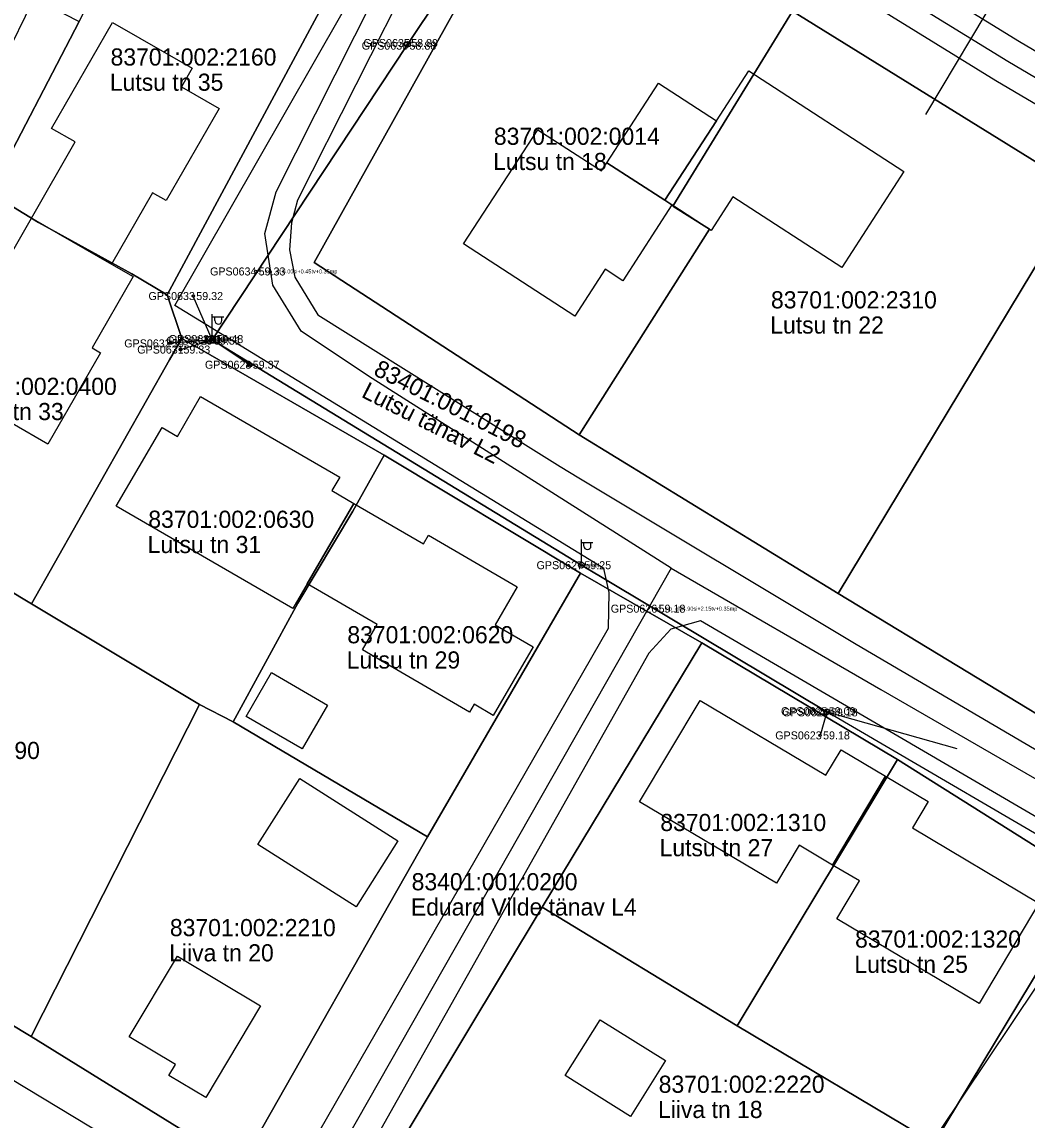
# Model space of a CAD drawing. Extents: x 580119 to 583377, y 6518915 to 6520820.
# Drawn here: x 581772.7 to 581860.5, y 6520277 to 6520373 of the extents above; entities that cross this region are included whole.
import ezdxf

# ---------------------------------------------------------------- set-up
doc = ezdxf.new("R2010")
doc.units = 0
for name, color, linetype in [('ELRAJATISMP', 7, 'Continuous'), ('Hoone Elu- või ühiskondlik hoone', 7, 'Continuous'), ('Hoone Kõrval- või tootmishoone', 7, 'Continuous'), ('L_AADRESS', 7, 'Continuous'), ('MAAMUDEL', 7, 'Continuous'), ('MOOTKORG-EH2000', 7, 'Continuous'), ('MOOTMPUNKT', 7, 'Continuous'), ('MOOTNR', 7, 'Continuous'), ('MPOHULIIN', 7, 'Continuous'), ('PIIR', 7, 'Continuous'), ('POST', 7, 'Continuous'), ('Rippe kõrgus', 7, 'Continuous'), ('SIOHULIIN', 7, 'Continuous'), ('SIRAJATIS', 7, 'Continuous'), ('Tee Liiklusala', 7, 'Continuous'), ('Tee Tänav Püsikate', 7, 'Continuous'), ('TUNNUS', 7, 'Continuous')]:
    doc.layers.add(name, color=color, linetype=linetype)

msp = doc.modelspace()

# ---------------------------------------------------------------- linework, layer by layer
at = {"layer": 'ELRAJATISMP'}
for p, q in [((581789.158, 6520345.511), (581789.158, 6520344.914)), ((581789.429, 6520345.511), (581789.429, 6520344.914))]:
    msp.add_line(p, q, dxfattribs=at)
msp.add_lwpolyline([(581788.696, 6520345.511), (581789.891, 6520345.511), (581789.891, 6520344.914), (581788.696, 6520344.914)], close=True, dxfattribs=at)
at = {"layer": 'Hoone Elu- või ühiskondlik hoone'}
for points in [[(581789.897, 6520365.456), (581785.267, 6520357.388), (581784.066, 6520358.074), (581780.484, 6520351.835), (581773.488, 6520355.852), (581777.309, 6520362.515), (581775.246, 6520363.708), (581780.566, 6520372.96), (581787.532, 6520368.967), (581786.605, 6520367.341)], [(581849.757, 6520359.929), (581844.318, 6520351.547), (581834.806, 6520357.717), (581832.902, 6520354.782), (581829.475, 6520357.006), (581828.842, 6520357.417), (581833.361, 6520364.377), (581836.189, 6520368.733)], [(581817.758, 6520363.59), (581823.32, 6520359.982), (581823.786, 6520360.7), (581828.842, 6520357.417), (581829.475, 6520357.006), (581825.18, 6520350.387), (581823.634, 6520351.39), (581820.977, 6520347.297), (581811.266, 6520353.598)], [(581782.362, 6520350.757), (581778.776, 6520344.511), (581779.521, 6520344.084), (581774.927, 6520336.097), (581771.788, 6520337.897), (581770.984, 6520336.504), (581764.038, 6520340.495), (581769.406, 6520349.847), (581769.887, 6520349.572), (581773.488, 6520355.852), (581780.484, 6520351.835)], [(581788.274, 6520340.264), (581800.435, 6520333.198), (581799.755, 6520332.025), (581801.668, 6520330.914), (581797.585, 6520323.885), (581796.321, 6520321.71), (581780.903, 6520330.666), (581784.9, 6520337.536), (581786.238, 6520336.758)], [(581801.668, 6520330.914), (581807.753, 6520327.378), (581808.187, 6520328.122), (581815.958, 6520323.603), (581814.029, 6520320.283), (581817.344, 6520318.359), (581813.862, 6520312.365), (581812.178, 6520313.343), (581811.785, 6520312.668), (581802.41, 6520318.115), (581803.699, 6520320.333), (581797.585, 6520323.885)], [(581831.936, 6520313.685), (581842.938, 6520307.135), (581844.272, 6520309.373), (581848.153, 6520307.062), (581843.524, 6520299.283), (581840.601, 6520301.023), (581838.615, 6520297.688), (581826.651, 6520304.808)], [(581861.562, 6520295.955), (581856.334, 6520287.167), (581843.894, 6520294.572), (581845.861, 6520297.893), (581843.524, 6520299.283), (581848.153, 6520307.062), (581851.891, 6520304.836), (581850.522, 6520302.527)], [(581793.512, 6520286.959), (581788.715, 6520278.954), (581785.489, 6520280.884), (581786.062, 6520281.845), (581782.021, 6520284.264), (581786.238, 6520291.31)]]:
    msp.add_lwpolyline(points, close=True, dxfattribs=at)
at = {"layer": 'Hoone Kõrval- või tootmishoone'}
for points in [[(581773.527, 6520374.677), (581771.164, 6520369.845), (581758.583, 6520375.994), (581760.951, 6520380.836)], [(581828.842, 6520357.417), (581823.786, 6520360.7), (581828.307, 6520367.654), (581833.361, 6520364.377)], [(581799.377, 6520313.278), (581797.15, 6520309.442), (581792.248, 6520312.288), (581794.476, 6520316.124)], [(581796.933, 6520306.849), (581805.518, 6520301.405), (581801.857, 6520295.631), (581793.272, 6520301.076)], [(581828.912, 6520282.18), (581825.861, 6520277.308), (581820.151, 6520280.885), (581823.202, 6520285.757)]]:
    msp.add_lwpolyline(points, close=True, dxfattribs=at)
at = {"layer": 'MOOTMPUNKT'}
for centre in [(581806.274, 6520370.939), (581806.424, 6520371.167), (581793.083, 6520351.193), (581787.632, 6520349.042), (581785.515, 6520344.9), (581789.188, 6520345.144), (581789.4, 6520345.282), (581786.511, 6520344.363), (581792.568, 6520343.035), (581821.56, 6520325.505), (581828.05, 6520321.704), (581842.927, 6520312.739), (581843.11, 6520312.635), (581842.429, 6520310.622)]:
    msp.add_circle(centre, 0.1, dxfattribs=at)
at = {"layer": 'MPOHULIIN'}
for p, q in [((581789.294, 6520345.213), (581787.632, 6520349.042)), ((581843.019, 6520312.687), (581842.429, 6520310.622))]:
    msp.add_line(p, q, dxfattribs=at)
for points in [[(581789.294, 6520345.213), (581806.349, 6520371.053), (581823.377, 6520396.506), (581838.047, 6520387.917), (581858.295, 6520376.01), (581878.688, 6520363.88), (581896.571, 6520352.922)], [(581867.762, 6520298.217), (581843.019, 6520312.687), (581821.56, 6520325.505), (581789.294, 6520345.213), (581785.515, 6520344.9)], [(581841.646, 6520259.228), (581850.68, 6520272.732), (581867.762, 6520298.217)]]:
    msp.add_lwpolyline(points, dxfattribs=at)
at = {"layer": 'PIIR'}
for points in [[(581744.38, 6520390.07), (581777.64, 6520373.06), (581769.84, 6520358.07), (581768.32, 6520355.34), (581735.49, 6520372.19)], [(581769.84, 6520358.07), (581777.64, 6520373.06), (581785.47, 6520388.28), (581801.36, 6520378.94), (581785.35, 6520349.14), (581782.27, 6520350.98), (581774.1, 6520355.46)], [(581817.44, 6520386.49), (581840.03, 6520373.94), (581829.56, 6520356.9), (581832.75, 6520354.9), (581821.38, 6520336.91), (581798.19, 6520351.98)], [(581798.19, 6520351.98), (581821.38, 6520336.91), (581844, 6520323.04), (581878.03, 6520302.4), (581885.96, 6520304.82), (581899.19, 6520326.8), (581895.57, 6520340), (581865.29, 6520358.29), (581840.03, 6520373.94), (581817.44, 6520386.49)], [(581832.75, 6520354.9), (581829.56, 6520356.9), (581840.03, 6520373.94), (581865.29, 6520358.29), (581844, 6520323.04), (581821.38, 6520336.91)], [(581759.06, 6520337.58), (581768.32, 6520355.34), (581769.84, 6520358.07), (581774.1, 6520355.46), (581782.27, 6520350.98), (581785.35, 6520349.14), (581786.62, 6520345.32), (581785.55, 6520343.45), (581773.48, 6520322.14), (581756.66, 6520332.23)], [(581865.29, 6520358.29), (581895.57, 6520340), (581899.19, 6520326.8), (581885.96, 6520304.82), (581878.03, 6520302.4), (581844, 6520323.04)], [(581785.55, 6520343.45), (581786.62, 6520345.32), (581804.32, 6520335.14), (581801.57, 6520330.22), (581796.78, 6520322.19), (581791.12, 6520311.82), (581788.16, 6520313.33), (581773.48, 6520322.14)], [(581796.78, 6520322.19), (581801.57, 6520330.22), (581804.32, 6520335.14), (581821.48, 6520324.8), (581808.12, 6520301.74), (581791.12, 6520311.82)], [(581773.48, 6520322.14), (581788.16, 6520313.33), (581773.45, 6520284.3), (581741.73, 6520303.41), (581756.66, 6520332.23)], [(581801.15, 6520267.32), (581791.76, 6520272.95), (581808.12, 6520301.74), (581821.48, 6520324.8), (581832.08, 6520318.73), (581818.12, 6520295.6)], [(581832.08, 6520318.73), (581849.2, 6520308.51), (581835.18, 6520285.22), (581818.12, 6520295.6)], [(581788.16, 6520313.33), (581791.12, 6520311.82), (581808.12, 6520301.74), (581791.76, 6520272.95), (581773.45, 6520284.3)], [(581849.2, 6520308.51), (581866.2, 6520297.82), (581852.4, 6520274.95), (581835.18, 6520285.22)], [(581866.2, 6520297.82), (581884.83, 6520286.51), (581870.83, 6520263.78), (581852.4, 6520274.95)], [(581818.12, 6520295.6), (581835.18, 6520285.22), (581852.4, 6520274.95), (581841.97, 6520255.88), (581832.33, 6520260.46), (581827.76, 6520250.96), (581804.72, 6520265.17), (581801.15, 6520267.32)]]:
    msp.add_lwpolyline(points, close=True, dxfattribs=at)
for points in [[(581953.73, 6520280.26), (581942.22, 6520287.85), (581915, 6520303.97), (581907.15, 6520308.24), (581895.61, 6520303.69), (581890.17, 6520295.02), (581885.52, 6520287.54), (581884.83, 6520286.51), (581866.2, 6520297.82), (581849.2, 6520308.51), (581832.08, 6520318.73), (581821.48, 6520324.8), (581804.32, 6520335.14), (581786.62, 6520345.32), (581785.35, 6520349.14), (581801.36, 6520378.94)], [(581641.44, 6520358.2), (581663.75, 6520346.68), (581696.78, 6520330.58), (581710.47, 6520322.41), (581741.73, 6520303.41), (581773.45, 6520284.3), (581791.76, 6520272.95), (581801.15, 6520267.32), (581804.72, 6520265.17), (581827.76, 6520250.96), (581836.91, 6520245.57), (581863.22, 6520229.79), (581868.94, 6520226.76), (581900.21, 6520207.51)]]:
    msp.add_lwpolyline(points, dxfattribs=at)
at = {"layer": 'POST'}
for p, q in [((581789.294, 6520345.463), (581789.294, 6520347.463)), ((581789.294, 6520347.213), (581790.294, 6520347.213)), ((581789.52, 6520346.892), (581789.52, 6520347.213)), ((581790.133, 6520346.892), (581790.133, 6520347.213)), ((581789.294, 6520345.213), (581789.294, 6520345.213)), ((581821.56, 6520325.755), (581821.56, 6520327.755)), ((581821.56, 6520327.505), (581822.56, 6520327.505)), ((581821.787, 6520327.184), (581821.787, 6520327.505)), ((581822.4, 6520327.184), (581822.4, 6520327.505)), ((581821.56, 6520325.505), (581821.56, 6520325.505))]:
    msp.add_line(p, q, dxfattribs=at)
for points in [[(581786.511, 6520344.363), (581789.294, 6520345.213)], [(581792.568, 6520343.035), (581789.294, 6520345.213)]]:
    msp.add_lwpolyline(points, dxfattribs=at)
for centre, radius in [((581806.349, 6520371.053), 0.25), ((581789.294, 6520345.213), 0.25), ((581786.511, 6520344.363), 0.125), ((581786.511, 6520344.363), 0.105), ((581786.511, 6520344.363), 0.0851), ((581786.511, 6520344.363), 0.0651), ((581786.511, 6520344.363), 0.0451), ((581786.511, 6520344.363), 0.0251), ((581786.511, 6520344.363), 0.00511), ((581792.568, 6520343.035), 0.2), ((581821.56, 6520325.505), 0.25), ((581843.019, 6520312.687), 0.25)]:
    msp.add_circle(centre, radius, dxfattribs=at)
for centre in [(581789.827, 6520346.892), (581822.093, 6520327.184)]:
    msp.add_arc(centre, 0.306, 180, 0, dxfattribs=at)
at = {"layer": 'SIOHULIIN'}
msp.add_line((581843.019, 6520312.687), (581854.376, 6520309.468), dxfattribs=at)
msp.add_lwpolyline([(581851.668, 6520364.915), (581858.295, 6520376.01), (581838.047, 6520387.917), (581823.377, 6520396.506), (581806.349, 6520371.053), (581789.294, 6520345.213), (581821.56, 6520325.505), (581843.019, 6520312.687)], dxfattribs=at)
at = {"layer": 'SIRAJATIS'}
msp.add_lwpolyline([(581788.794, 6520345.513), (581789.794, 6520345.513), (581789.794, 6520344.913), (581788.794, 6520344.913)], close=True, dxfattribs=at)
for centre, radius in [((581789.094, 6520345.213), 0.0304), ((581789.094, 6520345.213), 0.029), ((581789.094, 6520345.213), 0.0277), ((581789.094, 6520345.213), 0.0263), ((581789.094, 6520345.213), 0.0249), ((581789.094, 6520345.213), 0.0236), ((581789.094, 6520345.213), 0.0222), ((581789.094, 6520345.213), 0.0209), ((581789.094, 6520345.213), 0.0195), ((581789.094, 6520345.213), 0.0181), ((581789.094, 6520345.213), 0.0168), ((581789.094, 6520345.213), 0.0154), ((581789.094, 6520345.213), 0.014), ((581789.094, 6520345.213), 0.0127), ((581789.094, 6520345.213), 0.0113), ((581789.094, 6520345.213), 0.00996), ((581789.094, 6520345.213), 0.0086), ((581789.094, 6520345.213), 0.00724), ((581789.094, 6520345.213), 0.00587), ((581789.094, 6520345.213), 0.00451), ((581789.094, 6520345.213), 0.00315), ((581789.094, 6520345.213), 0.00179), ((581789.094, 6520345.213), 0.000426), ((581789.494, 6520345.213), 0.0304), ((581789.494, 6520345.213), 0.029), ((581789.494, 6520345.213), 0.0277), ((581789.494, 6520345.213), 0.0263), ((581789.494, 6520345.213), 0.0249), ((581789.494, 6520345.213), 0.0236), ((581789.494, 6520345.213), 0.0222), ((581789.494, 6520345.213), 0.0209), ((581789.494, 6520345.213), 0.0195), ((581789.494, 6520345.213), 0.0181), ((581789.494, 6520345.213), 0.0168), ((581789.494, 6520345.213), 0.0154), ((581789.494, 6520345.213), 0.014), ((581789.494, 6520345.213), 0.0127), ((581789.494, 6520345.213), 0.0113), ((581789.494, 6520345.213), 0.00996), ((581789.494, 6520345.213), 0.0086), ((581789.494, 6520345.213), 0.00724), ((581789.494, 6520345.213), 0.00587), ((581789.494, 6520345.213), 0.00451), ((581789.494, 6520345.213), 0.00315), ((581789.494, 6520345.213), 0.00179), ((581789.494, 6520345.213), 0.000426)]:
    msp.add_circle(centre, radius, dxfattribs=at)
at = {"layer": 'Tee Liiklusala'}
for points in [[(581708.973, 6520318.471), (581787.026, 6520271.325), (581789.162, 6520270.507), (581791.383, 6520270.184), (581793.899, 6520270.794), (581795.507, 6520271.692), (581797.15, 6520273.396), (581823.944, 6520319.987), (581823.993, 6520323.124), (581823.536, 6520325.218), (581786.005, 6520348.211), (581807.901, 6520386.495)], [(581843.846, 6520381.181), (581859.867, 6520371.288), (581885.234, 6520356.315), (581895.768, 6520349.311), (581899.82, 6520345.619), (581902.264, 6520341.18), (581903.771, 6520334.245), (581905.896, 6520322.742), (581907.129, 6520319.737), (581908.783, 6520316.908), (581910.786, 6520315.323), (581915.903, 6520312.25), (581921.785, 6520309.332), (581947.382, 6520293.091)], [(581806.937, 6520377.638), (581796.746, 6520357.421), (581796.211, 6520355.457), (581796.054, 6520353.093), (581796.496, 6520350.692), (581798.527, 6520347.398), (581811.066, 6520339.54), (581819.697, 6520334.131), (581821.327, 6520333.154), (581845.583, 6520318.613), (581875.933, 6520300.79)], [(581883.108, 6520352.925), (581857.799, 6520367.864), (581841.674, 6520377.821)], [(581883.73, 6520290.39), (581831.98, 6520320.646), (581829.373, 6520319.902), (581827.47, 6520317.82), (581801.546, 6520271.778), (581800.552, 6520269.623), (581800.234, 6520267.264), (581800.633, 6520264.933), (581801.205, 6520263.087), (581802.352, 6520262.069), (581822.226, 6520250.366), (581872.961, 6520219.702)]]:
    msp.add_lwpolyline(points, dxfattribs=at)
at = {"layer": 'Tee Tänav Püsikate'}
for points in [[(581829.397, 6520325.257), (581818.112, 6520332.413), (581802.942, 6520342.026), (581797.052, 6520345.979), (581794.581, 6520349.987), (581793.881, 6520354.518), (581794.87, 6520358.142), (581805.199, 6520378.634), (581809.475, 6520385.247), (581812.613, 6520388.504), (581816.168, 6520390.211), (581820.374, 6520391.246), (581824.109, 6520390.415), (581827.723, 6520388.924), (581832.69, 6520386.312), (581842.76, 6520379.501), (581858.833, 6520369.576), (581884.171, 6520354.62), (581894.534, 6520347.73), (581898.228, 6520344.364), (581900.371, 6520340.471), (581901.81, 6520333.851), (581904.244, 6520320.676), (581905.593, 6520312.247)], [(581829.397, 6520325.257), (581794.4, 6520263.722)], [(581829.397, 6520325.257), (581847.74, 6520314.641), (581881.43, 6520295.181), (581886.42, 6520300.232), (581896.888, 6520308.777), (581900.557, 6520310.703), (581905.593, 6520312.247)]]:
    msp.add_lwpolyline(points, dxfattribs=at)

# ---------------------------------------------------------------- texts
at = {"layer": 'L_AADRESS'}
for s, p in [('Lutsu tn 35', (581780.337, 6520366.992)), ('Lutsu tn 18', (581813.847, 6520360.061)), ('Lutsu tn 22', (581838.072, 6520345.758)), ('Lutsu tn 33', (581766.377, 6520338.193)), ('Lutsu tn 31', (581783.637, 6520326.568)), ('Lutsu tn 29', (581801.037, 6520316.47)), ('Lutsu tn 27', (581828.397, 6520300.053)), ('Eduard Vilde tänav L4', (581806.657, 6520294.871)), ('Liiva tn 20', (581785.522, 6520290.86)), ('Lutsu tn 25', (581845.427, 6520289.859)), ('Liiva tn 18', (581828.257, 6520277.162))]:
    msp.add_text(s, height=1.5, dxfattribs=at).set_placement(p)
msp.add_text('Lutsu tänav L2', height=1.5, rotation=333.18291, dxfattribs=at).set_placement((581802.242, 6520340.249))
at = {"layer": 'MAAMUDEL'}
for p in [(581789.188, 6520344.969), (581789.4, 6520345.107), (581821.56, 6520325.33)]:
    msp.add_text(' kaabel', height=0.35, dxfattribs=at).set_placement(p)
at = {"layer": 'MOOTKORG-EH2000'}
for s, p in [(' 58.89', (581806.424, 6520370.817)), (' 58.88', (581806.274, 6520370.589)), (' 59.33', (581793.083, 6520350.843)), (' 59.32', (581787.632, 6520348.692)), (' 59.48', (581789.4, 6520344.932)), (' 59.35', (581785.515, 6520344.55)), (' 59.33', (581786.511, 6520344.013)), (' 59.51', (581789.188, 6520344.794)), (' 59.37', (581792.568, 6520342.685)), (' 59.25', (581821.56, 6520325.155)), (' 59.18', (581828.05, 6520321.354)), (' 59.09', (581842.927, 6520312.389)), (' 59.18', (581843.11, 6520312.285)), (' 59.18', (581842.429, 6520310.272))]:
    msp.add_text(s, height=0.7, dxfattribs=at).set_placement(p)
at = {"layer": 'MOOTNR'}
for s, p in [('GPS0635 ', (581802.505, 6520370.817)), ('GPS0636 ', (581802.354, 6520370.589)), ('GPS0634 ', (581789.093, 6520350.843)), ('GPS0633 ', (581783.713, 6520348.692)), ('GPS0630 ', (581785.48, 6520344.932)), ('GPS0632 ', (581781.596, 6520344.55)), ('GPS0631 ', (581782.731, 6520344.013)), ('GPS0629 ', (581785.268, 6520344.794)), ('GPS0628 ', (581788.649, 6520342.685)), ('GPS0627 ', (581817.641, 6520325.155)), ('GPS0626 ', (581824.13, 6520321.354)), ('GPS0625 ', (581839.007, 6520312.389)), ('GPS0624 ', (581839.121, 6520312.285)), ('GPS0623 ', (581838.51, 6520310.272))]:
    msp.add_text(s, height=0.7, dxfattribs=at).set_placement(p)
at = {"layer": 'Rippe kõrgus'}
for s, p in [(' el_mp_ohl6.00si+0.45tv+0.35mp', (581793.083, 6520351.018)), (' el_mp_ohl4.90si+2.15tv+0.35mp', (581828.05, 6520321.529))]:
    msp.add_text(s, height=0.35, dxfattribs=at).set_placement(p)
at = {"layer": 'TUNNUS'}
for s, p in [('83701:002:2160', (581780.4, 6520369.197)), ('83701:002:0014', (581813.91, 6520362.266)), ('83701:002:2310', (581838.135, 6520347.963)), ('83701:002:0400', (581766.44, 6520340.398)), ('83701:002:0630', (581783.7, 6520328.773)), ('83701:002:0620', (581801.1, 6520318.676)), ('83701:002:0090', (581759.719, 6520308.557)), ('83701:002:1310', (581828.46, 6520302.258)), ('83401:001:0200', (581806.72, 6520297.076)), ('83701:002:2210', (581785.585, 6520293.065)), ('83701:002:1320', (581845.49, 6520292.064)), ('83701:002:2220', (581828.32, 6520279.367))]:
    msp.add_text(s, height=1.5, dxfattribs=at).set_placement(p)
msp.add_text('83401:001:0198', height=1.5, rotation=333.18291, dxfattribs=at).set_placement((581803.293, 6520342.189))

doc.saveas('drawing.dxf')
